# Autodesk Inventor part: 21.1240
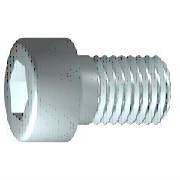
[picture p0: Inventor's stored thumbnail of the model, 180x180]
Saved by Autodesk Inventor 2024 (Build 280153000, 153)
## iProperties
Created: 2006-02
Part Number: 21.1240
Material: Steel, Mild
Description: M6x20 SHCS
Document SubType Name: Modeling
Standard: DIN 7984
Designer: Andy Moles
Standards Organization: DIN
Language: en-US
Size Designation: M6 x 20
Categories: <MemberInstance><Categories><Category DisplayName="Fasteners" InternalName="e4da775c-781d-43d5-af7c-5136215cf5a6" Mnemonic="FSTN"><Category DisplayName="Bolts"
Density: 7.86 g/cm^3
Vendor: S
Mass: 6.48581 g
Surface Area: 6.89561 cm^2
Volume: 0.825167 cm^3
Appearance: Zinc
Author: Andy Moles
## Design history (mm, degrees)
workplane "Work Plane1"
revolve "Body" stored, may be unused: angle "d10" = 90 deg
sketch "Sketch2"
  geometry: L1 (0, -7)-(0, 7) reference; L2 (-7, 0)-(7, 0) reference; L3 (2.309, 0)-(1.155, -2); L4 (1.155, -2)-(-1.155, -2); L5 (-1.155, -2)-(-2.309, 0); L6 (-2.309, 0)-(-1.155, 2); L7 (-1.155, 2)-(1.155, 2); L8 (1.155, 2)-(2.309, 0); 2 further points
  constraints: 12 end point, 1 coincident, 1 horizontal alignment, 1 point on line, 12 other
extrude "Slot" join sketch "Sketch2" stored distance "d11" = 10; taper "d12" = 0 deg
body "Solid1"
fillet "Fillet1" dims "d17" = 0.6 (= RR)
feature "Thread" dims "d13" = 20, "d14" = 0
chamfer "Chamfer1" distance "d15" = 0.61345 (= -0.5 x SPD + 0.5 x GD); stored, may be unused: second distance "d16" = 0.61345 (= GUL), angle "d27" = 45 deg
sketch "Sketch1"
  geometry: L1 (0.333, 0)-(20, 0); L2 (20, 0)-(20, 3); L3 (20, 3)-(3, 3); L4 (3, 3)-(2.386, 3); L5 (2.386, 3)-(0, 3); L6 (0, 3)-(0, 5); L7 (0, 5)-(-4, 5); L8 (-4, 5)-(-4, 2.309); L9 (-4, 2.309)-(-1, 2.309); L10 (-1, 2.309)-(0.333, 0); L11 (-8.8, 0)-(24.8, 0) reference; L12 (0, -1)-(0, 6) reference; L13 (3, 3)-(0, 3)
  constraints: 22 end point, 6 parallel, 2 collinear, 2 perpendicular, 1 horizontal, 1 point on line
  dimensions: "d1" = 17 distance from line of L3.end L2 (= GEL); "d2" = 0.61355 distance of L4.end L3.end (computed from GAL); "d3" = 4 distance between parallel lines of L8 L6 (= KOH); "d4" = 3 distance of L8.end L9.end (= INTI); "d5" = 60 deg angle of L10 L1; "d6" = 6 diameter of L3 L1 (= GD); "d7" = 6 diameter of L5 L1 (= BDM); "d8" = 4.6188 diameter of L9 L1 (= 1.1547 x SW); "d9" = 10 diameter of L7 L1 (= KOD); "d26" = 20 distance between parallel lines of L12 L2 (= NLG)
other parameters: "GD" = 6 (= NND) [user parameter; used in 2 equation terms], "NLG" = 20 [user parameter; used in 1 equation term], "GEL" = 17 [user parameter; used in 1 equation term], "KOD" = 10 [user parameter; used in 1 equation term], "KOH" = 4 [user parameter; used in 1 equation term], "INTI" = 3 [user parameter; used in 1 equation term], "GAL" = 0.61345 (= 0.61345 x PTC) [user parameter; used in 1 equation term], "GUL" = 0.61345 (= 0.61345 x PTC) [user parameter; used in 1 equation term], "BDM" = 6 (= NND) [user parameter; used in 1 equation term], "SW" = 4 [user parameter; used in 2 equation terms], "RR" = 0.6 [user parameter; used in 1 equation term], "SPD" = 4.7731 (= NND - 1.2269 x PTC) [user parameter; used in 1 equation term], "d19" = 0, "d28" = 0, "d29" = 0, "TOA" = 30 deg [user parameter], "GD1" = 4.7731 (= THREADDIA - 1.2269 x PTC) [user parameter], "THREADDIA" = 6 [user parameter; used in 1 equation term], "FAWI" = 45 deg [user parameter], "ANG" = 120 deg [user parameter], "PTC" = 1 [user parameter; used in 5 equation terms], "NND" = 6 [user parameter; used in 3 equation terms], "E0" = 4.62 (= 1.155 x SW) [user parameter]
